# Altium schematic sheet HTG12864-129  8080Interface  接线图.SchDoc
size A4
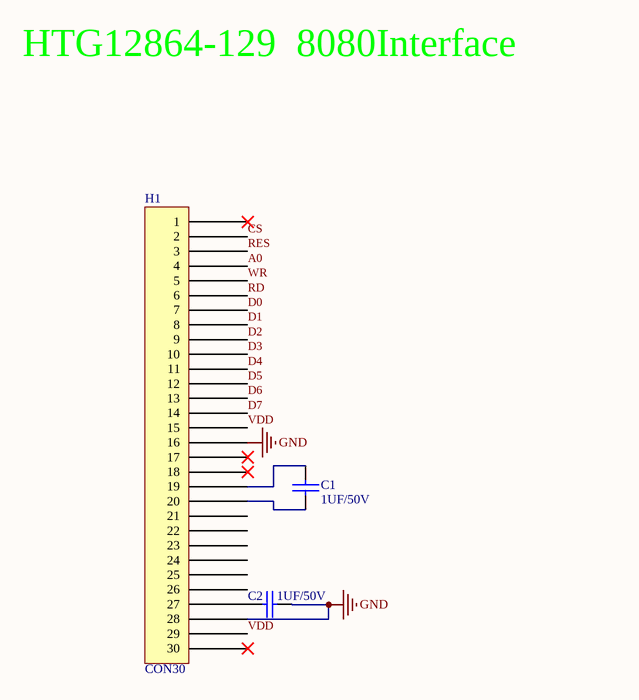
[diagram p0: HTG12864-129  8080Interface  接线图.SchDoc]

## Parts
C1  1UF/50V
C2  1UF/50V
H1  CON30

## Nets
GND: C2.2 H1.16 H1.28
A0: H1.4
CS: H1.2
D0: H1.7
D1: H1.8
D2: H1.9
D3: H1.10
D4: H1.11
D5: H1.12
D6: H1.13
D7: H1.14
RD: H1.6
RES: H1.3
VDD: H1.15 H1.29
WR: H1.5
NetC1_1: C1.1 H1.19
NetC1_2: C1.2 H1.20
NetC2_1: C2.1 H1.27

Not connected (* = marked no-connect by the designer): H1 1* 17* 18* 21 22 23 24 25 26 30*

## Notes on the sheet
- HTG12864-129  8080Interface

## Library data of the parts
C1 C2 = CAP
